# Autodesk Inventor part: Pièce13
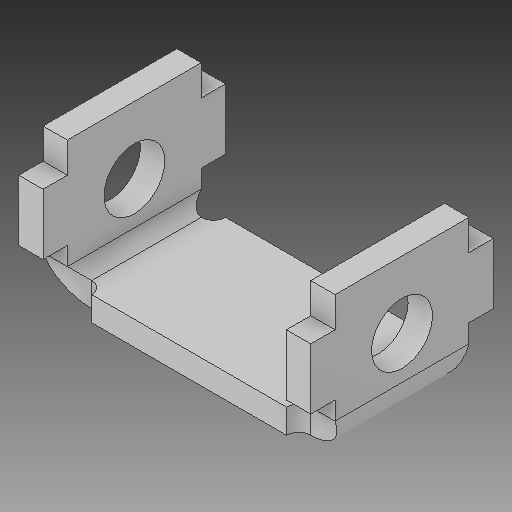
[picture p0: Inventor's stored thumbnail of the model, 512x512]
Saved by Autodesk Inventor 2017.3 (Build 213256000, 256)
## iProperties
Created: 2007-11
Part Number: Pièce13
Material: Générique
Document SubType Name: Modeling
Designer: ficho
Density: 1 g/cm^3
Appearance: Par défaut
Author: ficho
Sending System: SolidWorks 2009
Last Author: christophe
Last Saved: 2011-02-10
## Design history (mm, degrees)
feature "Symétrie8"
node "Solide1"
